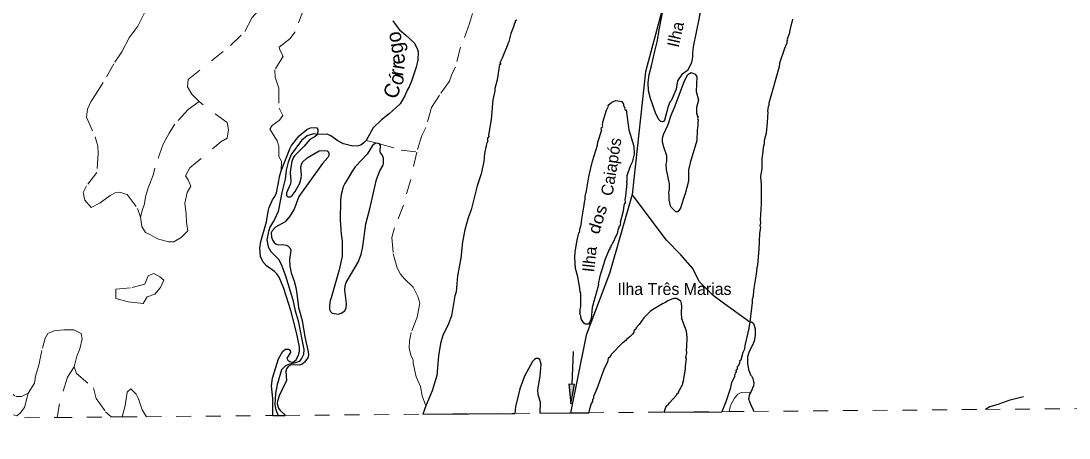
# Model space of a CAD drawing. Extents: x 344.9 to 371, y 7566.4 to 7594.3.
# Drawn here: x 359.71 to 366.76, y 7566.38 to 7569.18 of the extents above; entities that cross this region are included whole.
import ezdxf
from ezdxf.enums import TextEntityAlignment as Align

# ---------------------------------------------------------------- set-up
doc = ezdxf.new("R2010")
doc.units = 0
doc.header["$LTSCALE"] = 0.04
doc.linetypes.add('SHORT_DASHED', pattern=[2.7, 1.5, -1.2])
for name, color, linetype, lineweight in [('10', 7, 'Continuous', 25), ('17', 7, 'SHORT_DASHED', 13), ('2', 7, 'Continuous', 25), ('21', 7, 'SHORT_DASHED', 13), ('53', 7, 'SHORT_DASHED', 13), ('55', 7, 'Continuous', 25), ('7', 7, 'Continuous', 25)]:
    doc.layers.add(name, color=color, linetype=linetype, lineweight=lineweight)
doc.layers.add('61', color=7, linetype='Continuous')

msp = doc.modelspace()

# ---------------------------------------------------------------- hatches: boundary and pattern name
at = {"layer": '10'}
msp.add_hatch(color=256, dxfattribs=at).paths.add_polyline_path([(363.4106, 7566.612), (363.4341, 7566.7417), (363.3972, 7566.7432)])

# ---------------------------------------------------------------- linework, layer by layer
msp.add_line((363.4244, 7566.9645), (363.4157, 7566.7425), dxfattribs=at)
msp.add_lwpolyline([(363.4106, 7566.612), (363.4341, 7566.7417), (363.3972, 7566.7432)], close=True, dxfattribs=at)
at = {"layer": '17'}
for points in [[(362.7477, 7569.2343), (362.7292, 7569.1679), (362.6684, 7569.0092), (362.6333, 7568.8745), (362.6093, 7568.8265), (362.5927, 7568.7804), (362.5263, 7568.6863), (362.4728, 7568.6033), (362.4341, 7568.4677), (362.4082, 7568.416), (362.374, 7568.3041)], [(360.9097, 7568.6426), (360.8352, 7568.5901), (360.7474, 7568.4909), (360.7078, 7568.4314), (360.6682, 7568.3563), (360.6115, 7568.1947), (360.6002, 7568.1493), (360.5662, 7568.0628), (360.5492, 7568.0033), (360.5436, 7567.9551), (360.5294, 7567.9183), (360.5153, 7567.8666)], [(360.0697, 7566.8608), (360.0246, 7566.7921), (359.9708, 7566.6109), (359.9555, 7566.5203)], [(359.7609, 7566.6839), (359.7358, 7566.5883), (359.7075, 7566.5486), (359.6848, 7566.5316), (359.6367, 7566.5458), (359.5885, 7566.5713), (359.5432, 7566.6166), (359.4808, 7566.6583)]]:
    msp.add_lwpolyline(points, dxfattribs=at)
at = {"layer": '2'}
for p, q in [((362.4145, 7566.542), (363.033, 7566.5474)), ((363.2025, 7566.5489), (363.4067, 7566.5507)), ((363.4067, 7566.5507), (363.5305, 7566.5518)), ((364.0368, 7566.5561), (364.4239, 7566.5593)), ((361.4803, 7566.5453), (361.4876, 7566.5338))]:
    msp.add_line(p, q, dxfattribs=at)
for points in [[(363.9524, 7568.883), (363.9736, 7568.9812), (363.9934, 7569.0527), (364.003, 7569.1241), (364.0252, 7569.2385), (364.0371, 7569.2623), (364.1078, 7569.4481), (364.1205, 7569.4719), (364.2102, 7569.7245), (364.2197, 7569.7626), (364.2301, 7569.7816), (364.276, 7569.9417)], [(364.4799, 7569.93), (364.4596, 7569.8626), (364.4254, 7569.7785), (364.4127, 7569.7594), (364.3793, 7569.6895), (364.3611, 7569.6395), (364.3508, 7569.6228), (364.3444, 7569.5974), (364.3159, 7569.5458), (364.2833, 7569.4545), (364.2722, 7569.3973), (364.2817, 7569.329), (364.2793, 7569.2401), (364.2737, 7569.2242), (364.2729, 7569.2083), (364.2324, 7569.0098)], [(363.0469, 7569.1893), (363.0358, 7569.1829), (363.0358, 7569.1726), (363.031, 7569.1694), (363.0247, 7569.1448), (363.0064, 7569.1003), (362.9937, 7569.0471), (362.9897, 7569.0376), (362.985, 7569.0352), (362.9849, 7569.0288), (362.9468, 7568.9336), (362.9325, 7568.9042), (362.9357, 7568.9034), (362.9373, 7568.893), (362.9293, 7568.8923), (362.9151, 7568.789), (362.8992, 7568.7319), (362.8992, 7568.7128), (362.8849, 7568.6556), (362.8746, 7568.5222), (362.8563, 7568.4174), (362.8579, 7568.4055), (362.8539, 7568.4047), (362.8531, 7568.3991), (362.8499, 7568.3983), (362.8491, 7568.3705), (362.8436, 7568.3657), (362.8412, 7568.3475)], [(364.9011, 7569.1972), (364.8812, 7569.1225), (364.8788, 7569.0987), (364.8654, 7569.0622), (364.8669, 7569.0582), (364.8614, 7569.0511), (364.8622, 7569.036), (364.8463, 7569.0003), (364.8137, 7568.9002), (364.8097, 7568.8764), (364.7407, 7568.6318), (364.7407, 7568.6143), (364.7375, 7568.6095), (364.7327, 7568.5794), (364.7351, 7568.5746), (364.7303, 7568.5032), (364.7224, 7568.4317), (364.7089, 7568.3825), (364.7089, 7568.3586), (364.7025, 7568.3348), (364.6994, 7568.2872), (364.6946, 7568.2633), (364.6938, 7568.1903), (364.6859, 7568.1426), (364.6867, 7568.1045), (364.6898, 7568.0918), (364.6891, 7567.9552), (364.6835, 7567.8488), (364.6851, 7567.8273), (364.6803, 7567.8075), (364.6851, 7567.7996), (364.6787, 7567.7567), (364.6747, 7567.6519), (364.6652, 7567.5455)], [(364.2324, 7569.0098), (364.2269, 7568.9669), (364.2285, 7568.9463), (364.2205, 7568.9034), (364.1944, 7568.8525), (364.1554, 7568.824), (364.1268, 7568.7819), (364.1173, 7568.7255), (364.0832, 7568.6485), (364.0744, 7568.6389), (364.0633, 7568.6096), (364.0392, 7568.5181), (364.0332, 7568.5102), (364.0258, 7568.5067), (364.0152, 7568.5095), (364.0009, 7568.5229), (363.9811, 7568.5607), (363.9446, 7568.6636), (363.9321, 7568.7141), (363.9303, 7568.7711), (363.9372, 7568.8239), (363.9524, 7568.883)], [(364.0268, 7568.3713), (364.026, 7568.392), (364.0331, 7568.4222), (364.0649, 7568.4881), (364.0832, 7568.5524), (364.1102, 7568.6143), (364.1729, 7568.7827), (364.1959, 7568.824), (364.2182, 7568.8382), (364.2451, 7568.8279), (364.2579, 7568.8097), (364.2523, 7568.7096), (364.2682, 7568.6525), (364.2555, 7568.6032), (364.2555, 7568.5643), (364.2602, 7568.5524), (364.2586, 7568.5476), (364.261, 7568.5428), (364.265, 7568.542), (364.2618, 7568.5286), (364.2658, 7568.5182), (364.2626, 7568.5032), (364.2642, 7568.4793), (364.2594, 7568.4539), (364.2563, 7568.3809), (364.211, 7568.2316), (364.2015, 7568.1839), (364.1999, 7568.1077), (364.1792, 7568.0235), (364.1679, 7567.9911)], [(363.54, 7568.1776), (363.5551, 7568.2427), (363.5884, 7568.3507), (363.5908, 7568.3713), (363.617, 7568.4539), (363.6146, 7568.4555), (363.6162, 7568.4682), (363.6202, 7568.469), (363.625, 7568.4769), (363.6226, 7568.4817), (363.625, 7568.5048), (363.6504, 7568.5857), (363.6623, 7568.6127), (363.6599, 7568.6191), (363.6846, 7568.6381), (363.7131, 7568.6508), (363.7536, 7568.6437), (363.7639, 7568.6246), (363.7648, 7568.6159), (363.7719, 7568.6016), (363.7711, 7568.596), (363.7759, 7568.5873), (363.7806, 7568.5865), (363.8005, 7568.4523), (363.8338, 7568.3443), (363.8362, 7568.2903), (363.8227, 7568.2363), (363.8076, 7568.2094), (363.7854, 7568.1442), (363.7862, 7568.1117), (363.783, 7568.1006), (363.7854, 7568.0958), (363.7782, 7568.0092), (363.7727, 7567.9807), (363.7759, 7567.9711), (363.7743, 7567.9592), (363.7703, 7567.9584), (363.7663, 7567.9441), (363.7608, 7567.906), (363.7409, 7567.8298), (363.7441, 7567.821), (363.7385, 7567.8051), (363.733, 7567.8043), (363.733, 7567.7909), (363.7282, 7567.7901), (363.7203, 7567.7575), (363.6853, 7567.6805)], [(361.4611, 7568.1777), (361.5197, 7568.326), (361.5317, 7568.3477), (361.5829, 7568.4124), (361.6332, 7568.4556), (361.6586, 7568.4676), (361.6858, 7568.4699), (361.7019, 7568.4658), (361.7088, 7568.4556), (361.707, 7568.4214)], [(361.707, 7568.4214), (361.6913, 7568.4085), (361.6553, 7568.3891), (361.6156, 7568.3436), (361.552, 7568.2788), (361.5419, 7568.264), (361.5331, 7568.2393), (361.5234, 7568.1888), (361.5211, 7568.162), (361.5275, 7568.112), (361.5243, 7568.0896), (361.4971, 7568.0296), (361.498, 7568.0125), (361.5068, 7568.0028), (361.5211, 7568.0033)], [(361.5211, 7568.0033), (361.5349, 7568.012), (361.5557, 7568.0381), (361.5861, 7568.0942), (361.5953, 7568.1279), (361.5976, 7568.1507), (361.5948, 7568.1994), (361.599, 7568.2211), (361.6059, 7568.2363), (361.6359, 7568.2656), (361.7176, 7568.3111), (361.7333, 7568.3148), (361.7716, 7568.3125), (361.7785, 7568.307), (361.7822, 7568.2959), (361.7817, 7568.2809), (361.7766, 7568.2675), (361.7406, 7568.2262), (361.58, 7568.0042), (361.5491, 7567.9211), (361.521, 7567.8738), (361.4891, 7567.8345), (361.4241, 7567.7983), (361.402, 7567.775), (361.3951, 7567.7616), (361.3974, 7567.7328), (361.4057, 7567.7092), (361.415, 7567.6958), (361.4288, 7567.685), (361.4449, 7567.6813), (361.4703, 7567.6818), (361.4952, 7567.6783), (361.5086, 7567.6713), (361.5197, 7567.6593), (361.5261, 7567.6441), (361.5169, 7567.5809), (361.5192, 7567.5364), (361.5284, 7567.4923), (361.5492, 7567.4371), (361.5593, 7567.3939), (361.5676, 7567.3507), (361.5782, 7567.2598), (361.6031, 7567.1721), (361.6214, 7567.0618), (361.6441, 7566.9617), (361.645, 7566.9414), (361.6399, 7566.9213), (361.6182, 7566.8913), (361.6025, 7566.8775), (361.5845, 7566.8719), (361.5425, 7566.8745), (361.5236, 7566.8722), (361.5089, 7566.8629), (361.4978, 7566.8461), (361.4941, 7566.8313), (361.4978, 7566.766), (361.4881, 7566.751), (361.4475, 7566.6647), (361.4365, 7566.6303), (361.4355, 7566.6127), (361.4443, 7566.5825), (361.4544, 7566.5677), (361.4803, 7566.5453)], [(361.9129, 7568.1275), (361.8894, 7568.0935), (361.8788, 7568.0697), (361.8655, 7568.0192), (361.8613, 7567.9797), (361.8581, 7567.8456), (361.8645, 7567.7524), (361.8728, 7567.7051), (361.8719, 7567.6036), (361.8516, 7567.5127), (361.7989, 7567.3243), (361.7911, 7567.3063), (361.786, 7567.2733), (361.7869, 7567.2456), (361.7929, 7567.2322), (361.8039, 7567.2221), (361.8464, 7567.2154), (361.8648, 7567.2209), (361.8888, 7567.2377), (361.898, 7567.2571), (361.9007, 7567.2864), (361.8892, 7567.3755), (361.8915, 7567.4055), (361.8998, 7567.4274), (361.98, 7567.5647), (361.9998, 7567.6162), (362.0118, 7567.6695), (362.0321, 7567.8207), (362.0588, 7567.9227), (362.1021, 7568.1183), (362.1256, 7568.1772), (362.1468, 7568.2148), (362.1505, 7568.2291), (362.1505, 7568.2635), (362.1412, 7568.2847), (362.1302, 7568.2981), (362.1274, 7568.3094), (362.1292, 7568.3472), (362.1223, 7568.3601), (362.1076, 7568.3638)], [(362.1076, 7568.3638), (362.0937, 7568.362), (362.0749, 7568.3469), (362.0393, 7568.2895), (361.9595, 7568.2043), (361.9369, 7568.1711), (361.9129, 7568.1275)], [(362.8412, 7568.3475), (362.8301, 7568.2935), (362.8245, 7568.2395), (362.8055, 7568.1585), (362.7801, 7568.0775), (362.7396, 7567.9155), (362.7189, 7567.8615), (362.6967, 7567.7805), (362.6816, 7567.6995), (362.6689, 7567.5916), (362.6467, 7567.4724), (362.6379, 7567.3644), (362.63, 7567.3374), (362.6062, 7567.204), (362.5871, 7567.15), (362.549, 7567.0706), (362.5323, 7567.0166), (362.5188, 7566.9356), (362.5077, 7566.8022), (362.4773, 7566.6997), (362.4335, 7566.5986), (362.4145, 7566.542)], [(364.1679, 7567.9911), (364.1475, 7567.9267), (364.13, 7567.902), (364.1158, 7567.9028), (364.1086, 7567.9084), (364.0847, 7567.9338), (364.08, 7567.9433), (364.0704, 7567.983), (364.0712, 7568.014), (364.0681, 7568.0331), (364.0728, 7568.0521), (364.0736, 7568.0902), (364.053, 7568.1855), (364.0506, 7568.2221), (364.0562, 7568.2411), (364.0554, 7568.2792), (364.0339, 7568.3364), (364.0268, 7568.3713)], [(361.4062, 7566.5331), (361.4054, 7566.6472), (361.3976, 7566.734), (361.4027, 7566.7836), (361.4438, 7566.9146), (361.4732, 7566.9657), (361.4898, 7566.98), (361.5106, 7566.98), (361.5212, 7566.9726), (361.5244, 7566.9578), (361.5, 7566.9197), (361.506, 7566.9059), (361.5198, 7566.8957), (361.5323, 7566.892), (361.5443, 7566.8941), (361.5622, 7566.907), (361.5807, 7566.9446), (361.5848, 7566.9654), (361.5839, 7566.9942), (361.5659, 7567.0921), (361.5272, 7567.2397), (361.4802, 7567.3872), (361.4479, 7567.4631), (361.4327, 7567.485), (361.417, 7567.5002), (361.3626, 7567.5397), (361.3409, 7567.5628), (361.322, 7567.6018), (361.3178, 7567.6574), (361.3247, 7567.7038), (361.3639, 7567.8346), (361.3736, 7567.905), (361.3805, 7567.9306), (361.404, 7567.9834), (361.4197, 7568.0042), (361.4303, 7568.0307), (361.4519, 7568.1452), (361.4611, 7568.1777)], [(363.5003, 7567.9473), (363.5011, 7567.9664), (363.5066, 7567.9854), (363.5051, 7568.0045), (363.5154, 7568.0426), (363.5305, 7568.1379), (363.54, 7568.1776)], [(363.6853, 7567.6805), (363.6782, 7567.6733), (363.679, 7567.6654), (363.6718, 7567.6598), (363.671, 7567.6495), (363.6671, 7567.6487), (363.6408, 7567.5836), (363.6043, 7567.4693), (363.5932, 7567.4169), (363.5956, 7567.4161), (363.5948, 7567.4121), (363.5527, 7567.2596), (363.5456, 7567.1834), (363.5345, 7567.1604), (363.536, 7567.158), (363.5281, 7567.1476), (363.5075, 7567.1468), (363.4972, 7567.154), (363.4797, 7567.1834), (363.4773, 7567.2025), (363.4701, 7567.2167), (363.4749, 7567.2318), (363.4709, 7567.2342), (363.4765, 7567.266), (363.4757, 7567.3588), (363.4725, 7567.3596), (363.4709, 7567.3883), (363.4574, 7567.4645), (363.4415, 7567.5217), (363.4368, 7567.5963), (363.4391, 7567.6344), (363.4519, 7567.7107), (363.4638, 7567.7615), (363.4693, 7567.767), (363.4677, 7567.7758), (363.4709, 7567.7781), (363.4725, 7567.7948), (363.4789, 7567.8139), (363.4828, 7567.852), (363.5003, 7567.9473)], [(364.6652, 7567.5455), (364.6597, 7567.5248), (364.6565, 7567.4836), (364.6382, 7567.3756), (364.635, 7567.3343), (364.6295, 7567.3136), (364.6295, 7567.293), (364.6136, 7567.1614)], [(364.0368, 7566.5561), (364.0482, 7566.5894), (364.0586, 7566.6021), (364.0641, 7566.6045), (364.0721, 7566.618), (364.1197, 7566.6712), (364.1252, 7566.6815), (364.1348, 7566.687), (364.1332, 7566.6934), (364.1618, 7566.7442), (364.1618, 7566.7593), (364.1697, 7566.7633), (364.1673, 7566.7689), (364.1808, 7566.8451), (364.18, 7566.8642), (364.1872, 7566.9174), (364.1832, 7566.9237), (364.1888, 7566.9547), (364.1864, 7566.9753), (364.1904, 7566.996), (364.1927, 7567.0579), (364.1872, 7567.0992), (364.1554, 7567.1834), (364.1538, 7567.2247), (364.157, 7567.266), (364.1546, 7567.2866), (364.1483, 7567.3033), (364.1435, 7567.3072), (364.1205, 7567.3199), (364.0999, 7567.3199), (364.0625, 7567.3048), (364.0459, 7567.2929), (364.0252, 7567.285), (363.9585, 7567.2445), (363.9426, 7567.2318), (363.8997, 7567.1889), (363.8696, 7567.1461), (363.8465, 7567.1206), (363.8489, 7567.1198), (363.8458, 7567.1143), (363.8338, 7567.1024), (363.8338, 7567.0921), (363.8243, 7567.0809), (363.8061, 7567.0611), (363.7838, 7567.0436), (363.7798, 7567.0365), (363.7592, 7567.0222), (363.756, 7567.0229), (363.6814, 7566.9436), (363.6814, 7566.9396), (363.6734, 7566.9332), (363.6734, 7566.9269), (363.6607, 7566.9174), (363.6567, 7566.8943), (363.6305, 7566.8419)], [(364.6136, 7567.1614), (364.6017, 7567.0968), (364.5985, 7567.0945), (364.6009, 7567.0889), (364.5795, 7567.0039), (364.5771, 7566.9801), (364.566, 7566.9579), (364.5517, 7566.9046), (364.5437, 7566.8999), (364.5469, 7566.8912), (364.5358, 7566.8657), (364.5287, 7566.8602), (364.5271, 7566.8427), (364.5199, 7566.8371), (364.5223, 7566.8268), (364.5143, 7566.8189), (364.5096, 7566.8006), (364.512, 7566.7982), (364.4897, 7566.7546), (364.4802, 7566.7133), (364.4508, 7566.6259), (364.4239, 7566.5593)], [(363.2025, 7566.5489), (363.2051, 7566.6231), (363.189, 7566.6728), (363.188, 7566.7071), (363.2023, 7566.7971), (363.2101, 7566.8777), (363.2, 7566.9091), (363.1889, 7566.9155), (363.1764, 7566.9165), (363.1644, 7566.9109), (363.1529, 7566.8973), (363.0971, 7566.7972), (363.0675, 7566.7117), (363.0364, 7566.5921), (363.033, 7566.5474)], [(363.6305, 7566.8419), (363.5853, 7566.7133), (363.5622, 7566.6609), (363.5614, 7566.6474), (363.5543, 7566.641), (363.5543, 7566.6275), (363.5432, 7566.61), (363.5448, 7566.6061), (363.5329, 7566.5688), (363.5305, 7566.5518)], [(361.4062, 7566.5331), (361.4425, 7566.5334), (361.4876, 7566.5338)]]:
    msp.add_lwpolyline(points, dxfattribs=at)
at = {"layer": '21'}
msp.add_line((362.0328, 7568.3825), (362.1076, 7568.3638), dxfattribs=at)
for points in [[(360.9097, 7568.6426), (360.8607, 7568.6936), (360.8312, 7568.7427), (360.8371, 7568.7917), (361.1216, 7569.0194), (361.2178, 7569.1135), (361.2649, 7569.2048), (361.3414, 7569.2911), (361.4022, 7569.3696), (361.4709, 7569.4343), (361.5749, 7569.6207), (361.6985, 7569.7326), (361.8182, 7569.8199), (361.8672, 7569.8493)], [(360.2111, 7568.6867), (360.2872, 7568.8092), (360.3421, 7568.9073), (360.3892, 7568.9779), (360.4383, 7569.0701), (360.4972, 7569.1506), (360.5443, 7569.2428)], [(361.6141, 7569.2666), (361.5552, 7569.1126), (361.5199, 7569.0655), (361.4473, 7569.0086), (361.4503, 7568.9945), (361.4748, 7568.9478), (361.4198, 7568.8555), (361.4218, 7568.8065), (361.4453, 7568.7329), (361.4473, 7568.5995), (361.4728, 7568.5504), (361.4512, 7568.5171), (361.4002, 7568.4818), (361.3865, 7568.4582), (361.4355, 7568.3797), (361.4453, 7568.3435), (361.4453, 7568.2748), (361.463, 7568.2434), (361.4611, 7568.1777)], [(360.2111, 7568.6867), (360.1817, 7568.6406), (360.1601, 7568.5915), (360.1522, 7568.5386), (360.2111, 7568.4051), (360.2288, 7568.3423), (360.2307, 7568.2933), (360.2229, 7568.1658), (360.1523, 7568.0765), (360.1307, 7568.0314), (360.1425, 7567.9804), (360.1837, 7567.9313), (360.2445, 7567.9627), (360.3112, 7568.0118), (360.3446, 7568.0294), (360.374, 7568.0334), (360.427, 7568.0177), (360.4956, 7567.9254), (360.5153, 7567.8666)], [(360.5153, 7567.8666), (360.5251, 7567.8038), (360.5486, 7567.7626), (360.5839, 7567.7469), (360.6291, 7567.7204), (360.7036, 7567.7008), (360.739, 7567.7008), (360.79, 7567.7302), (360.8331, 7567.7753), (360.8253, 7567.8322), (360.8233, 7567.8872), (360.8135, 7567.9598), (360.8292, 7568.0324), (360.8547, 7568.0755), (360.8371, 7568.1167), (360.8174, 7568.1442), (360.8469, 7568.1972), (361.0549, 7568.3719), (361.0981, 7568.3974), (361.1079, 7568.4523), (361.0981, 7568.5014), (360.9097, 7568.6426)], [(362.1223, 7568.3601), (362.2689, 7568.3171), (362.374, 7568.3041)], [(362.374, 7568.3041), (362.3334, 7568.1196), (362.2836, 7567.948), (362.2246, 7567.7949), (362.2061, 7567.7294), (362.2154, 7567.6206), (362.2412, 7567.5265), (362.2633, 7567.484), (362.291, 7567.4508), (362.3501, 7567.3955), (362.3814, 7567.3337), (362.3943, 7567.2894), (362.3759, 7567.1953), (362.3353, 7567.092), (362.3242, 7567.0348), (362.3224, 7566.985), (362.3334, 7566.9388), (362.3482, 7566.9056), (362.35, 7566.8853), (362.3703, 7566.794), (362.398, 7566.7294), (362.4109, 7566.6667), (362.4335, 7566.5986)], [(359.1987, 7567.4136), (359.2503, 7567.4023), (359.2955, 7567.3691), (359.3362, 7567.3225), (359.3603, 7567.2727), (359.4025, 7567.1357), (359.4446, 7567.0423), (359.4597, 7566.9971), (359.5079, 7566.8932), (359.5139, 7566.8315), (359.5877, 7566.7215), (359.6781, 7566.6613), (359.7158, 7566.6613), (359.7609, 7566.6839)], [(359.7609, 7566.6839), (359.8031, 7566.7516), (359.8106, 7566.7983), (359.8317, 7566.8721), (359.8558, 7566.9858), (359.8754, 7567.0521), (359.8919, 7567.0837), (359.9356, 7567.1033), (360.0004, 7567.1093), (360.0667, 7567.1093), (360.1164, 7567.0852), (360.1239, 7567.0491), (360.1073, 7566.9813), (360.0878, 7566.9316), (360.0697, 7566.8608)], [(360.0697, 7566.8608), (360.0862, 7566.8156), (360.1992, 7566.7185), (360.2173, 7566.6477), (360.2805, 7566.5588), (360.3174, 7566.5235)], [(360.3928, 7566.5242), (360.4116, 7566.598), (360.4266, 7566.6914), (360.4507, 7566.7124), (360.4869, 7566.6778), (360.5019, 7566.6447), (360.5261, 7566.5709), (360.5559, 7566.5256)], [(364.62, 7566.6911), (364.5559, 7566.6874), (364.5332, 7566.6772), (364.5104, 7566.6489), (364.4877, 7566.609), (364.4799, 7566.5909), (364.4747, 7566.5598)]]:
    msp.add_lwpolyline(points, dxfattribs=at)
msp.add_lwpolyline([(360.3488, 7567.3198), (360.3488, 7567.3814), (360.4604, 7567.3926), (360.5442, 7567.415), (360.5665, 7567.471), (360.6056, 7567.4878), (360.6447, 7567.4654), (360.6726, 7567.443), (360.6503, 7567.3926), (360.6112, 7567.3478), (360.5609, 7567.331), (360.533, 7567.2862), (360.4325, 7567.2974)], close=True, dxfattribs=at)
at = {"layer": '53'}
for points in [[(361.4876, 7566.5338), (362.4145, 7566.542), (363.033, 7566.5474), (363.2025, 7566.5489), (363.4067, 7566.5507), (363.5305, 7566.5518), (364.0368, 7566.5561), (364.4239, 7566.5593), (364.4747, 7566.5598), (364.6393, 7566.5612), (366.1971, 7566.5742), (370.9611, 7566.6143)], [(345.1495, 7566.3822), (350.2712, 7566.4313), (351.2121, 7566.4404), (351.9925, 7566.4478), (354.437, 7566.4703), (355.6028, 7566.481), (355.7769, 7566.4826), (358.4581, 7566.5071), (358.8284, 7566.5104), (359.123, 7566.513), (359.2531, 7566.5141), (359.5359, 7566.5166), (359.9555, 7566.5203), (360.3174, 7566.5235), (360.3928, 7566.5242), (360.5559, 7566.5256), (361.4062, 7566.5331)], [(361.4062, 7566.5331), (361.4425, 7566.5334), (361.4876, 7566.5338)]]:
    msp.add_lwpolyline(points, dxfattribs=at)
at = {"layer": '55'}
for points in [[(364.2487, 7569.9432), (364.0895, 7569.5068), (363.9121, 7568.8431), (363.8211, 7568.0189), (363.6699, 7567.4867), (363.5122, 7567.0727), (363.4067, 7566.5507)], [(361.707, 7568.4214), (361.6798, 7568.4273), (361.6355, 7568.4125), (361.598, 7568.3817), (361.5296, 7568.2877), (361.5081, 7568.2368), (361.4947, 7568.1818), (361.4893, 7568.1214), (361.4665, 7568.0328), (361.4426, 7567.9035), (361.4171, 7567.8498), (361.3862, 7567.7988), (361.3755, 7567.7693), (361.3647, 7567.7143), (361.3741, 7567.666), (361.3916, 7567.6352), (361.4452, 7567.5828), (361.464, 7567.5439), (361.4882, 7567.4782), (361.5404, 7567.3118), (361.5565, 7567.2366), (361.5766, 7567.1695), (361.6142, 7566.9764), (361.6129, 7566.9442), (361.5995, 7566.916), (361.582, 7566.8972), (361.5579, 7566.8878), (361.5109, 7566.8771), (361.4908, 7566.8677), (361.464, 7566.8395), (361.4346, 7566.7424), (361.4226, 7566.682), (361.4185, 7566.6042), (361.4266, 7566.572), (361.4425, 7566.5334)], [(364.6136, 7567.1614), (364.4444, 7567.2813), (364.3658, 7567.3392), (364.2744, 7567.4309), (364.2287, 7567.5226), (364.1503, 7567.6142), (364.0524, 7567.7124), (363.8211, 7568.0189)]]:
    msp.add_lwpolyline(points, dxfattribs=at)
at = {"layer": '7'}
for points in [[(362.2133, 7569.1856), (362.2272, 7569.1621), (362.2576, 7569.1241), (362.2997, 7569.0884)], [(362.2997, 7569.0884), (362.356, 7569.0368), (362.3767, 7568.9987), (362.3826, 7568.9772), (362.3798, 7568.9244), (362.3687, 7568.8748), (362.337, 7568.7795), (362.3227, 7568.7421), (362.3084, 7568.7192), (362.2925, 7568.681), (362.2615, 7568.627), (362.187, 7568.5602), (362.1369, 7568.5206), (362.0813, 7568.4674), (362.0328, 7568.3825)], [(362.0328, 7568.3825), (362.0177, 7568.3658), (362.0007, 7568.353), (361.9813, 7568.3451), (361.944, 7568.3443), (361.8812, 7568.3586), (361.8438, 7568.3785), (361.7946, 7568.4134), (361.77, 7568.4229), (361.707, 7568.4214)], [(364.6136, 7567.1614), (364.6247, 7567.162), (364.639, 7567.152), (364.6501, 7567.1153), (364.6493, 7567.0738), (364.6414, 7567.0309), (364.6382, 7567.0278), (364.6351, 7567.0127), (364.6303, 7567.0079), (364.6065, 7566.9563), (364.5969, 7566.9277), (364.5969, 7566.8848), (364.6033, 7566.8419), (364.6176, 7566.8078), (364.6255, 7566.8006), (364.6343, 7566.7816), (364.6398, 7566.7498), (364.6382, 7566.7339), (364.62, 7566.6911)], [(364.62, 7566.6911), (364.6112, 7566.6768), (364.6049, 7566.645), (364.6168, 7566.6093), (364.6343, 7566.5767), (364.6393, 7566.5612)], [(366.4527, 7566.6593), (366.3551, 7566.6354), (366.282, 7566.6069), (366.2264, 7566.591), (366.1971, 7566.5742)]]:
    msp.add_lwpolyline(points, dxfattribs=at)

# ---------------------------------------------------------------- texts
at = {"layer": '61'}
for s, height, rotation, p in [('Ilha', 0.08, 77.308, (364.153, 7569.0862)), ('ego', 0.1, 99.318, (362.2803, 7569.0098)), ('rr', 0.1, 81.145, (362.288, 7568.8538)), ('Có', 0.1, 69.617, (362.2659, 7568.7331)), ('Caiapós', 0.08, 81.058, (363.7203, 7568.1989)), ('Ilha', 0.08, 83.676, (363.5754, 7567.5792))]:
    msp.add_text(s, height=height, rotation=rotation, dxfattribs=at).set_placement(p, align=Align.CENTER)
at = {"layer": '61', "width": 1.15}
msp.add_text('dos', height=0.08, rotation=72.663, dxfattribs=at).set_placement((363.6266, 7567.8401), align=Align.CENTER)
at = {"layer": '61'}
msp.add_text('Ilha Três Marias', height=0.08, dxfattribs=at).set_placement((364.1066, 7567.3437), align=Align.CENTER)

doc.saveas('drawing.dxf')
